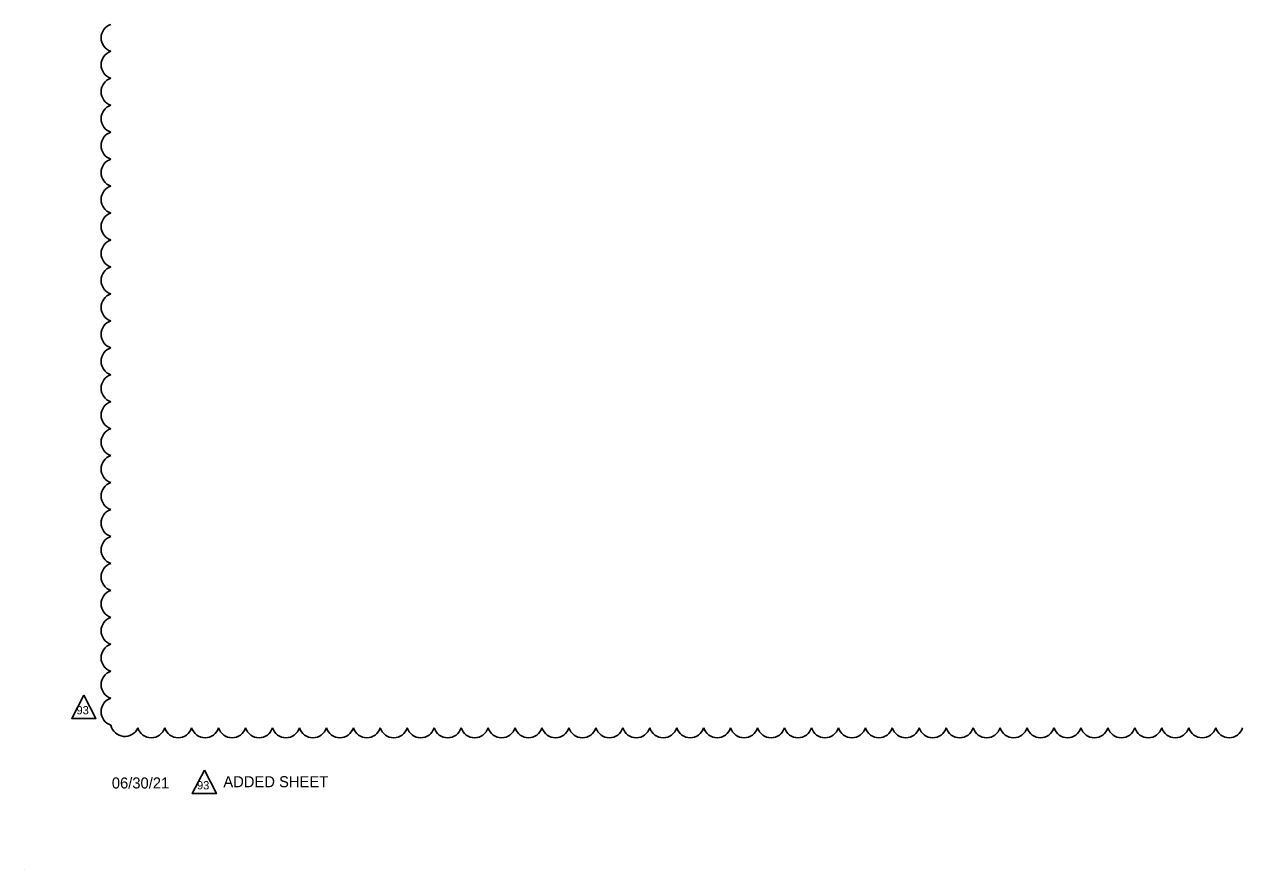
# Model space of a CAD drawing. Extents: x -811.3 to -795.2, y -2199.5 to -2188.9.
# Drawn here: x -811.34 to -803.6, y -2199.5 to -2194.13 of the extents above; entities that cross this region are included whole.
import ezdxf

# ---------------------------------------------------------------- set-up
doc = ezdxf.new("R2010")
doc.units = 0
for name, color, linetype in [('ScratchEle_dp', 7, 'Continuous'), ('TextMinor', 7, 'Continuous'), ('TextTitle', 7, 'Continuous')]:
    doc.layers.add(name, color=color, linetype=linetype)

msp = doc.modelspace()

# ---------------------------------------------------------------- linework, layer by layer
at = {"layer": 'ScratchEle_dp'}
for centre, radius, start, end in [((-810.7588, -2194.2199), 0.0897, 107.5, 252.5), ((-810.7588, -2194.391), 0.0897, 107.5, 252.5), ((-810.7588, -2194.5621), 0.0897, 107.5, 252.5), ((-810.7588, -2194.7332), 0.0897, 107.5, 252.5), ((-810.7588, -2194.9044), 0.0897, 107.5, 252.5), ((-810.7588, -2195.0755), 0.0897, 107.5, 252.5), ((-810.7588, -2195.2466), 0.0897, 107.5, 252.5), ((-810.7588, -2195.4177), 0.0897, 107.5, 252.5), ((-810.7588, -2195.5889), 0.0897, 107.5, 252.5), ((-810.7588, -2195.76), 0.0897, 107.5, 252.5), ((-810.7588, -2195.9311), 0.0897, 107.5, 252.5), ((-810.7588, -2196.1022), 0.0897, 107.5, 252.5), ((-810.7588, -2196.2733), 0.0897, 107.5, 252.5), ((-810.7588, -2196.4445), 0.0897, 107.5, 252.5), ((-810.7588, -2196.6156), 0.0897, 107.5, 252.5), ((-810.7588, -2196.7867), 0.0897, 107.5, 252.5), ((-810.7588, -2196.9578), 0.0897, 107.5, 252.5), ((-810.7588, -2197.129), 0.0897, 107.5, 252.5), ((-810.7588, -2197.3001), 0.0897, 107.5, 252.5), ((-810.7588, -2197.4712), 0.0897, 107.5, 252.5), ((-810.7588, -2197.6423), 0.0897, 107.5, 252.5), ((-810.7588, -2197.8134), 0.0897, 107.5, 252.5), ((-810.7588, -2197.9846), 0.0897, 107.5, 252.5), ((-810.7588, -2198.1557), 0.0897, 107.5, 252.5), ((-810.7588, -2198.3268), 0.0897, 107.5, 252.5), ((-810.7588, -2198.4979), 0.0897, 107.5, 252.5), ((-810.698, -2198.5653), 0.0896, 191.74536, 336.74536), ((-810.5301, -2198.5737), 0.0897, 197.5, 342.5), ((-810.359, -2198.5737), 0.0897, 197.5, 342.5), ((-810.1879, -2198.5737), 0.0897, 197.5, 342.5), ((-810.0167, -2198.5737), 0.0897, 197.5, 342.5), ((-809.8456, -2198.5737), 0.0897, 197.5, 342.5), ((-809.6745, -2198.5737), 0.0897, 197.5, 342.5), ((-809.5034, -2198.5737), 0.0897, 197.5, 342.5), ((-809.3323, -2198.5737), 0.0897, 197.5, 342.5), ((-809.1611, -2198.5737), 0.0897, 197.5, 342.5), ((-808.99, -2198.5737), 0.0897, 197.5, 342.5), ((-808.8189, -2198.5737), 0.0897, 197.5, 342.5), ((-808.6478, -2198.5737), 0.0897, 197.5, 342.5), ((-808.4766, -2198.5737), 0.0897, 197.5, 342.5), ((-808.3055, -2198.5737), 0.0897, 197.5, 342.5), ((-808.1344, -2198.5737), 0.0897, 197.5, 342.5), ((-807.9633, -2198.5737), 0.0897, 197.5, 342.5), ((-807.7921, -2198.5737), 0.0897, 197.5, 342.5), ((-807.621, -2198.5737), 0.0897, 197.5, 342.5), ((-807.4499, -2198.5737), 0.0897, 197.5, 342.5), ((-807.2788, -2198.5737), 0.0897, 197.5, 342.5), ((-807.1077, -2198.5737), 0.0897, 197.5, 342.5), ((-806.9365, -2198.5737), 0.0897, 197.5, 342.5), ((-806.7654, -2198.5737), 0.0897, 197.5, 342.5), ((-806.5943, -2198.5737), 0.0897, 197.5, 342.5), ((-806.4232, -2198.5737), 0.0897, 197.5, 342.5), ((-806.252, -2198.5737), 0.0897, 197.5, 342.5), ((-806.0809, -2198.5737), 0.0897, 197.5, 342.5), ((-805.9098, -2198.5737), 0.0897, 197.5, 342.5), ((-805.7387, -2198.5737), 0.0897, 197.5, 342.5), ((-805.5676, -2198.5737), 0.0897, 197.5, 342.5), ((-805.3964, -2198.5737), 0.0897, 197.5, 342.5), ((-805.2253, -2198.5737), 0.0897, 197.5, 342.5), ((-805.0542, -2198.5737), 0.0897, 197.5, 342.5), ((-804.8831, -2198.5737), 0.0897, 197.5, 342.5), ((-804.7119, -2198.5737), 0.0897, 197.5, 342.5), ((-804.5408, -2198.5737), 0.0897, 197.5, 342.5), ((-804.3697, -2198.5737), 0.0897, 197.5, 342.5), ((-804.1986, -2198.5737), 0.0897, 197.5, 342.5), ((-804.0275, -2198.5737), 0.0897, 197.5, 342.5), ((-803.8563, -2198.5737), 0.0897, 197.5, 342.5), ((-803.6852, -2198.5737), 0.0897, 197.5, 342.5)]:
    msp.add_arc(centre, radius, start, end, dxfattribs=at)
at = {"layer": 'TextMinor'}
for points in [[(-810.9581, -2198.3928), (-811.0351, -2198.5411), (-810.8811, -2198.5411)], [(-810.1928, -2198.8692), (-810.2698, -2199.0175), (-810.1158, -2199.0175)]]:
    msp.add_lwpolyline(points, close=True, dxfattribs=at)
at = {"layer": 'TextTitle'}
msp.add_line((-811.3358, -2199.5006), (-811.3358, -2199.5006), dxfattribs=at)

# ---------------------------------------------------------------- texts
at = {"layer": 'ScratchEle_dp'}
for s, p in [('06/30/21', (-810.7803, -2198.9855)), ('ADDED SHEET', (-810.0721, -2198.9774))]:
    msp.add_text(s, height=0.07, rotation=0, dxfattribs=at).set_placement(p)
at = {"layer": 'TextMinor'}
for p in [(-811.0047, -2198.5147), (-810.2395, -2198.9912)]:
    msp.add_text('93', height=0.0525, rotation=360, dxfattribs=at).set_placement(p)

doc.saveas('drawing.dxf')
